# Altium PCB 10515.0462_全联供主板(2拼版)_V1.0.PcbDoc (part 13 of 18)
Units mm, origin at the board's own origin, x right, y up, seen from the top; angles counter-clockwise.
Board outline 282 x 198 mm, 2 copper layers (Top Layer, Bottom Layer); 716 components, 0 nets, 2364 pads, 1800 vias.
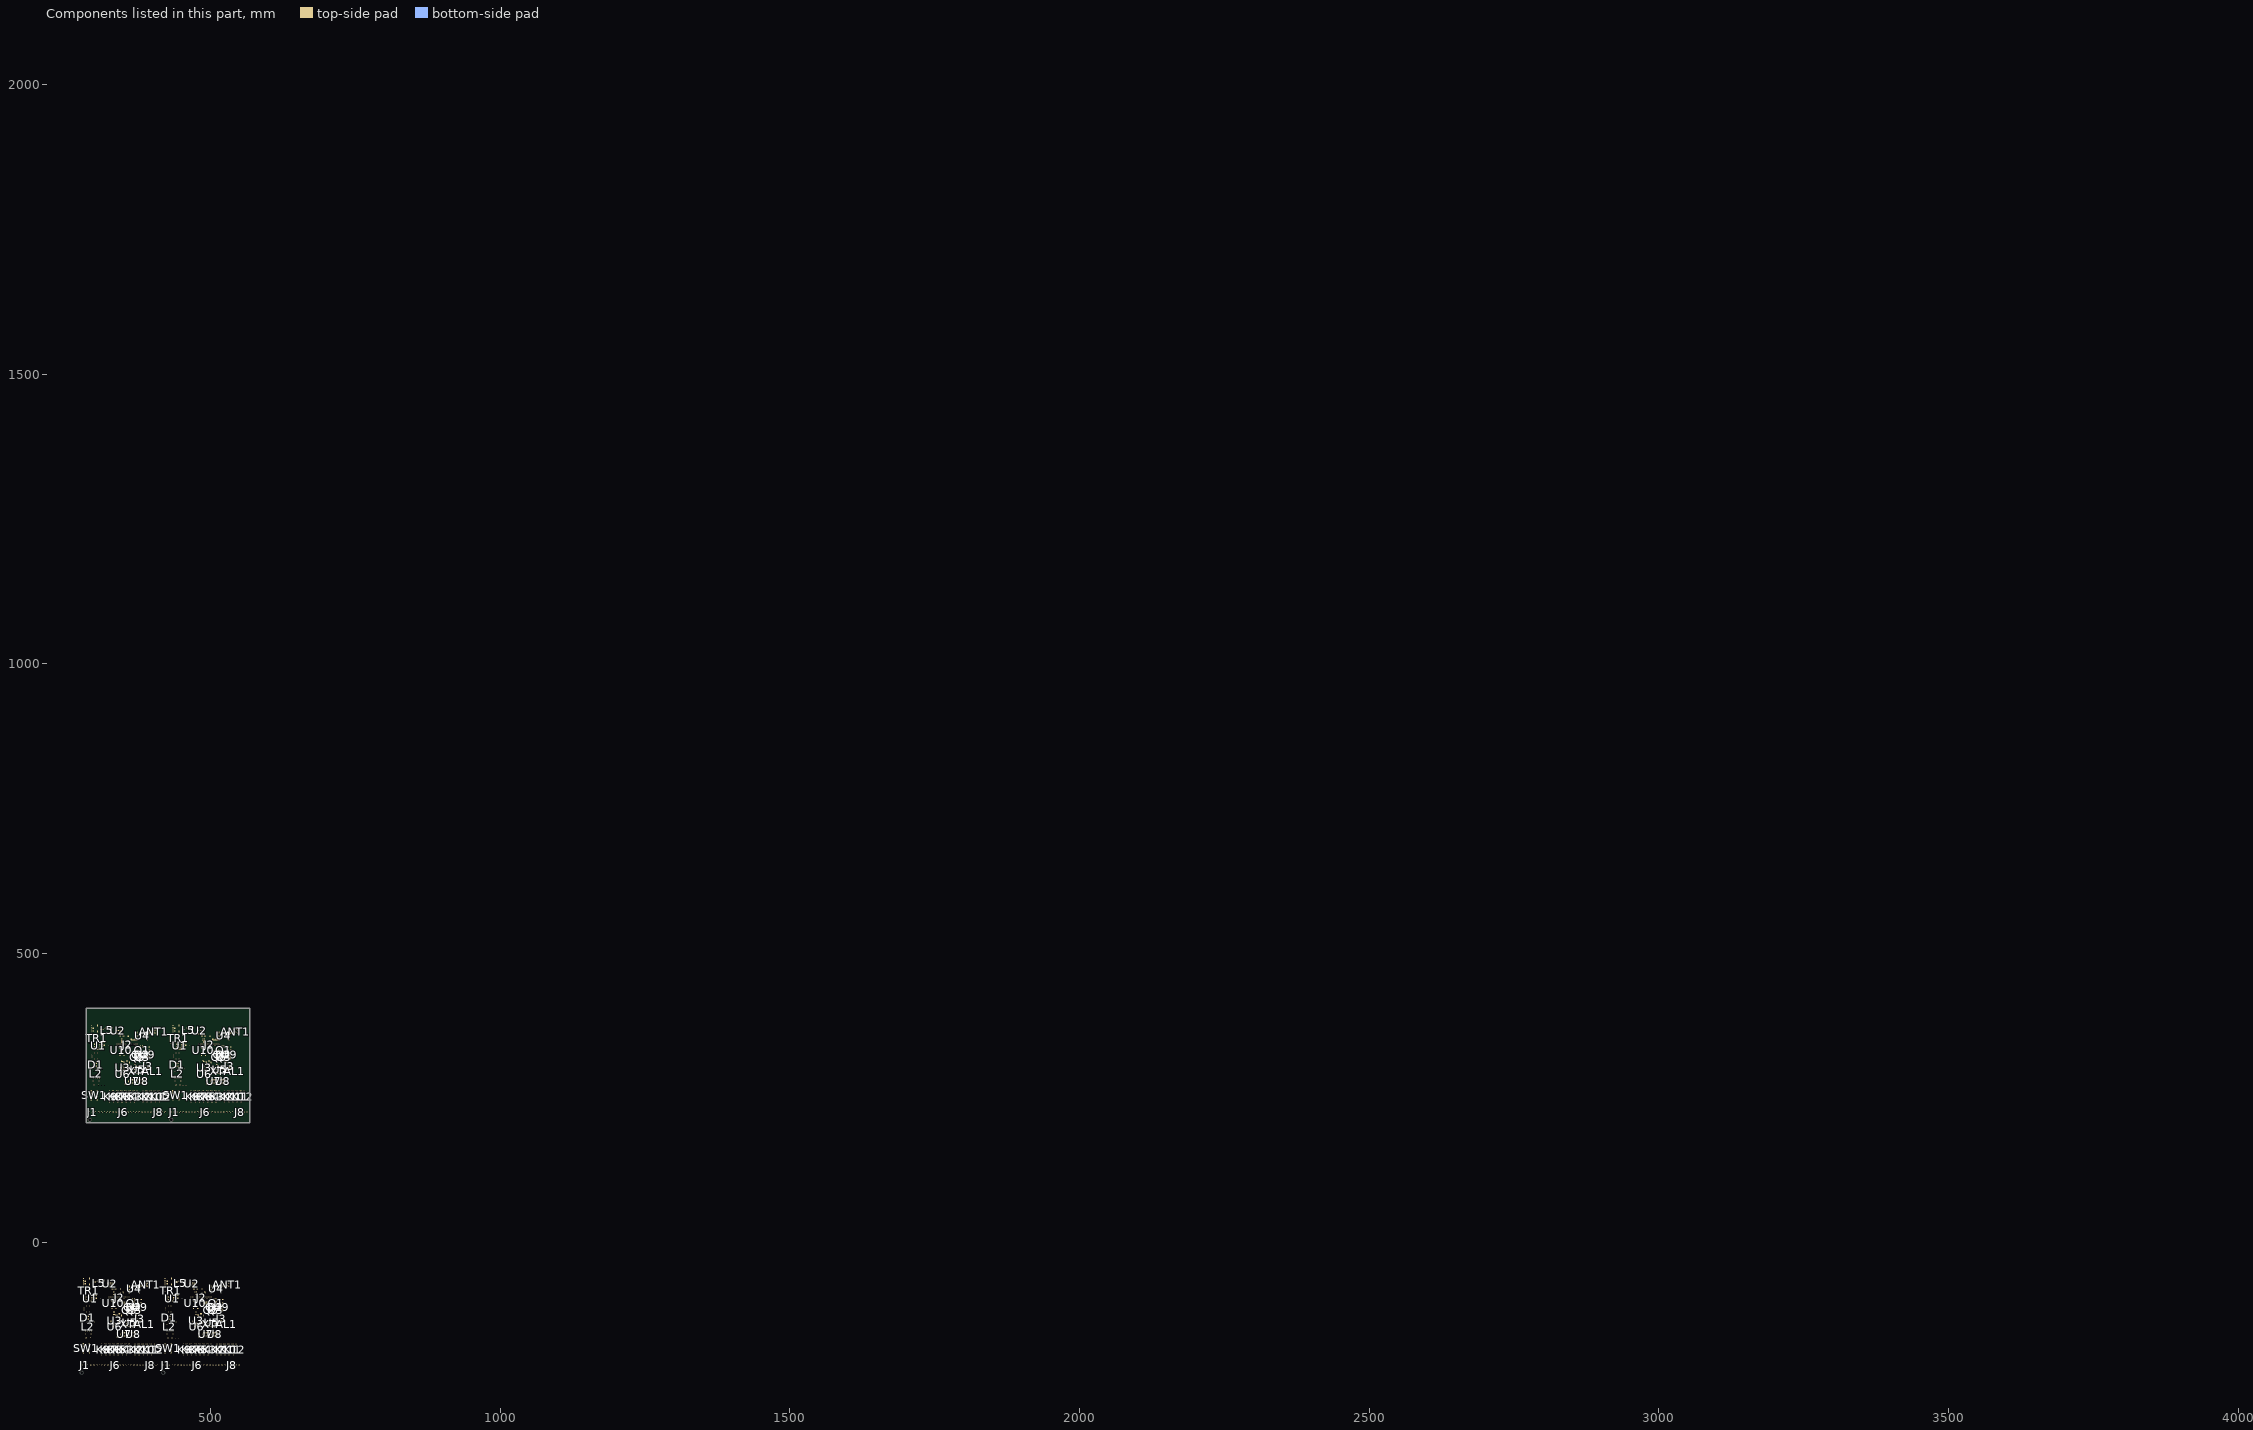
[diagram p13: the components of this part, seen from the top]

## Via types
v1: diameter 0.7, hole 0.4, Top Layer to Bottom Layer, tented both sides, 1800 vias

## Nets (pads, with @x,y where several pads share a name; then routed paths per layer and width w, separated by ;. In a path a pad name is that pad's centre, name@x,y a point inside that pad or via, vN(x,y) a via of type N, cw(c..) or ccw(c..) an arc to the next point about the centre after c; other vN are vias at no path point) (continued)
copper on no net: (continued)
  Top Layer w1.5: 274.137,-177.275 274.137,-179.477 ; 274.3,-175.667 278.491,-175.667 278.999,-176.175 278.11,-177.064 274.808,-177.064 ; 276.55,-177.064 275.298,-178.316 ; 277.951,-137.313 cw(c277.951,-134.711) 276.111,-136.551 ; 278.257,-135.662 ccw(c278.257,-138.697) 276.111,-136.551 ; 278.364,-174.397 274.681,-174.397 273.665,-175.413 273.665,-197.511 281.476,-205.321 ; 278.745,-178.334 278.727,-178.316 275.298,-178.316 ; 278.999,-188.113 280.142,-189.256 280.142,-192.304 ; 280.024,-67.088 280.024,-64.528 ; 280.024,-61.099 282.69,-61.099 283.554,-61.963 283.554,-65.748 ; 280.049,-70.542 283.548,-70.542 ; 280.142,-194.209 280.65,-194.209 288.016,-201.575 ; 280.557,-93.529 283.28,-93.529 ; 280.65,-135.535 284.587,-131.598 285.984,-131.598 285.984,-131.852 282.174,-135.662 277,-135.662 276.111,-136.551 ; 280.86,-139.301 ccw(c283.699,-136.462) 283.699,-140.477 ; 281.192,-115.353 283.317,-115.353 ; 281.192,-112.353 284.401,-112.353 285.677,-111.077 285.677,-108.622 285.677,-109.486 282.809,-112.353 ; 281.301,-138.329 279.888,-138.329 ; 282.809,-211.227 282.809,-205.418 274.137,-196.746 274.137,-179.477 ; v1(283.318,-126.457) 286.088,-126.457 ; 283.326,-93.484 283.326,-90.106 283.605,-89.826 ; 283.326,-90.622 cw(c284.4,-90.622) 283.64,-89.862 ; 283.554,-75.776 283.554,-70.548 ; 283.571,-147.855 283.571,-151.664 283.571,-156.871 ; 283.942,-66.066 cw(c286.674,-68.798) 286.674,-64.934 ; 284.097,-162.546 ccw(c284.951,-161.692) 284.951,-162.899 ; 284.887,-116.924 cw(c283.101,-118.709) 285.627,-118.709 ; 285.123,-110.04 ccw(c283.905,-108.822) 285.627,-108.822 ; 285.54,-202.781 285.54,-202.913 286.391,-203.764 286.391,-210.295 287.081,-210.984 ; 285.677,-118.009 285.677,-117.713 283.317,-115.353 ; 285.727,-119.109 ccw(c289.195,-119.109) 286.743,-121.562 ; 287,-151.664 290.683,-151.664 ; 287.766,259.32 287.766,257.118 ; 287.929,260.928 292.12,260.928 292.628,260.42 291.739,259.531 288.437,259.531 ; 288.917,-126.487 288.917,-123.736 285.677,-120.496 285.677,-118.909 285.677,-116.432 284.599,-115.353 283.317,-115.353 ; 289.286,-132.741 290.175,-133.63 ; 289.298,-132.437 cw(c289.298,-134.248) 290.578,-132.968 ; 289.425,-131.687 291.368,-133.63 ; 289.499,-171.689 284.951,-167.14 ; 289.499,-170.546 288.461,-169.507 ; 289.774,-176.449 288.461,-175.136 288.461,-172.238 ; 289.858,-185.255 290.366,-185.763 300.272,-185.763 ; 289.921,-189.256 302.665,-189.256 ; 290.048,-133.63 291.114,-133.63 ; 290.134,-185.614 290.134,-186.04 290.769,-186.675 301.944,-186.675 304.802,-183.817 ; 290.179,259.531 288.927,258.279 ; 290.261,-185.614 291.064,-184.811 ; 290.302,-184.811 303.808,-184.811 ; 290.677,-109.373 291.953,-110.649 291.953,-117.633 290.677,-118.909 290.677,-108.622 ; 290.677,-102.486 290.677,-108.622 ; 290.727,-108.822 ccw(c292.177,-108.822) 291.152,-109.848 ; 290.81,-187.986 302.582,-187.986 307.066,-183.502 ; 290.86,-133.63 293.604,-133.63 ; 290.89,-62.383 288.339,-64.934 287.762,-64.934 ; 291.58,299.282 cw(c291.58,301.884) 289.74,300.044 ; 291.699,-147.977 cw(c291.699,-151.647) 294.294,-149.052 ; 291.699,-147.727 292.969,-147.727 294.112,-148.87 294.112,-151.664 294.112,-156.465 292.352,-158.225 292.352,-164.566 ; 291.728,-140.479 ccw(c292.133,-136.985) 294.62,-139.472 ; 291.785,-147.962 cw(c292.382,-149.584) 293.604,-148.362 ; 291.886,300.933 ccw(c291.886,297.898) 289.74,300.044 ; 291.993,262.198 288.31,262.198 287.294,261.182 287.294,239.084 295.104,231.274 ; 292.023,-103.601 297.611,-103.601 ; 292.175,-164.14 ccw(c288.479,-160.444) 293.706,-160.444 ; 292.207,-105.055 293.477,-105.055 291.699,-103.277 291.699,-107.214 ; 292.352,-164.066 ccw(c292.352,-162.859) 293.205,-163.713 ; 292.374,258.261 292.356,258.279 288.927,258.279 ; 292.461,-213.398 cw(c295.375,-213.398) 293.315,-211.338 ; 292.461,-103.601 ccw(c292.461,-99.86) 295.106,-102.505 ; 292.628,248.482 293.771,247.339 293.771,244.291 ; 292.961,-218.816 292.961,-217.45 ; 293.059,-102.505 ccw(c295.704,-99.86) 295.704,-103.601 ; 293.527,-156.692 ccw(c292.113,-155.278) 294.112,-155.278 ; 293.652,369.508 293.652,372.068 ; 293.652,375.497 296.319,375.497 297.183,374.633 297.183,370.848 ; 293.678,366.053 297.177,366.053 ; 293.706,-156.871 293.706,-163.212 292.352,-164.566 ; 293.771,242.386 294.279,242.386 301.645,235.02 ; 294.186,343.066 296.909,343.066 ; 294.279,301.06 298.216,304.997 299.613,304.997 299.613,304.743 295.803,300.933 290.629,300.933 289.74,300.044 ; 294.489,297.294 ccw(c297.328,300.133) 297.328,296.118 ; 294.821,321.242 296.946,321.242 ; 294.821,324.242 298.029,324.242 299.306,325.518 299.306,327.973 299.306,327.11 296.438,324.242 ; 294.93,298.266 293.517,298.266 ; 295.21,-102.497 ccw(c297.611,-100.438) 297.611,-103.601 ; 296.438,225.368 296.438,231.177 287.766,239.849 287.766,257.118 ; v1(296.947,310.139) 299.717,310.139 ; 296.954,343.112 296.954,346.49 297.234,346.769 ; 296.954,345.974 cw(c298.029,345.974) 297.269,346.734 ; 297.183,360.82 297.183,366.048 ; 297.2,288.74 297.2,284.931 297.2,279.724 ; 297.571,370.529 cw(c300.303,367.798) 300.303,371.661 ; 297.726,274.05 ccw(c298.579,274.903) 298.579,273.696 ; 297.795,-164.491 297.72,-164.566 ; 297.961,-210.984 297.961,-208.439 311.671,-194.729 311.671,-192.812 ; 298.516,319.672 cw(c296.73,317.886) 299.256,317.886 ; 298.684,-138.71 ccw(c297.023,-137.048) 299.319,-136.551 ; 298.752,326.556 ccw(c297.534,327.773) 299.256,327.773 ; 299.008,-102.204 297.611,-103.601 ; 299.168,233.814 299.168,233.683 300.02,232.831 300.02,226.301 300.71,225.611 ; 299.306,318.586 299.306,318.882 296.946,321.242 ; 299.356,317.486 ccw(c302.824,317.486) 300.372,315.034 ; 299.573,-186.675 299.573,-186.462 ; 300.629,284.931 304.312,284.931 ; 300.97,-219.314 301.426,-218.858 ; 301.138,-186.675 302.875,-184.938 ; 302.05,-185.763 300.272,-185.763 ; 302.157,-186.462 299.573,-186.462 ; 302.211,-81.208 ccw(c303.675,-79.744) v1@303.675,-81.814 ; v1@302.514,-81.199 303.129,-81.814 305.542,-81.814 312.781,-81.814 ; 302.546,310.108 302.546,312.86 299.306,316.1 299.306,317.686 299.306,320.164 298.227,321.242 296.946,321.242 ; 302.875,-169.825 302.875,-164.491 ; 302.915,303.854 303.804,302.965 ; 302.927,304.158 cw(c302.927,302.347) 304.207,303.628 ; 302.961,-218.656 302.961,-217.323 ; 302.961,-210.984 302.961,-217.323 ; 303.054,304.908 304.996,302.965 ; 303.128,264.906 298.579,269.455 ; 303.128,266.049 302.089,267.088 ; 303.402,260.146 302.089,261.459 302.089,264.357 ; 303.453,-82.138 ccw(c303.637,-81.953) 303.637,-82.214 ; 303.486,251.34 303.994,250.832 313.9,250.832 ; 303.55,247.339 316.294,247.339 ; 303.677,302.965 304.742,302.965 ; 303.763,250.981 303.763,250.555 304.398,249.92 315.573,249.92 318.431,252.778 ; 303.88,-174.905 303.88,-174.016 ; 303.89,250.981 304.693,251.784 ; 303.931,251.784 317.437,251.784 ; 303.944,-73.666 cw(c301.467,-76.143) 304.971,-76.143 ; 304.306,327.222 305.582,325.946 305.582,318.962 304.306,317.686 304.306,327.973 ; 304.306,334.109 304.306,327.973 ; 304.356,327.773 ccw(c305.806,327.773) 304.78,326.748 ; 304.439,248.609 316.211,248.609 320.695,253.093 ; 304.488,302.965 307.233,302.965 ; 304.519,374.212 301.967,371.661 301.391,371.661 ; 305.328,288.618 cw(c305.328,284.949) 307.923,287.544 ; 305.328,288.868 306.598,288.868 307.741,287.725 307.741,284.931 307.741,280.131 305.98,278.37 305.98,272.029 ; 305.357,296.117 ccw(c305.762,299.61) 308.249,297.123 ; 305.414,288.634 cw(c306.01,287.011) 307.233,288.234 ; 305.437,-183.944 306.031,-184.537 ; 305.652,332.994 311.24,332.994 ; 305.804,272.456 ccw(c302.108,276.152) 307.334,276.152 ; 305.836,331.54 307.106,331.54 305.328,333.318 305.328,329.381 ; 305.923,-179.477 305.288,-178.842 ; 305.98,272.529 ccw(c305.98,273.736) 306.834,272.883 ; 306.006,-182.779 305.923,-182.696 304.802,-183.817 ; 306.09,332.994 ccw(c306.09,336.735) 308.735,334.09 ; 306.09,223.197 cw(c309.004,223.197) 306.943,225.258 ; 306.094,-183.966 313.543,-183.966 ; 306.304,-79.274 304.971,-77.94 ; 306.59,217.779 306.59,219.145 ; 306.688,334.09 ccw(c309.333,336.735) 309.333,332.994 ; 307.155,279.904 ccw(c305.742,281.317) 307.741,281.317 ; 307.334,279.724 307.334,273.383 305.98,272.029 ; 307.657,-186.252 314.051,-186.252 ; 307.955,-183.966 302.665,-189.256 ; 307.961,-210.984 307.961,-206.694 318.856,-195.799 318.856,-192.939 ; 308.574,-182.255 306.453,-182.255 ; 308.839,334.098 ccw(c311.24,336.157) 311.24,332.994 ; 308.971,-183.966 308.971,-184.938 304.653,-189.256 303.764,-189.256 ; 309.098,-182.779 307.066,-180.747 ; 310.484,-185.065 375.508,-185.065 ; 311.424,272.104 311.348,272.029 ; 311.59,225.611 311.59,228.156 325.3,241.866 325.3,243.783 ; 311.671,-186.252 314.051,-186.252 ; 311.765,-185.827 311.765,-185.7 ; 311.765,-183.541 306.05,-189.256 303.764,-189.256 ; 311.777,-186.008 cw(c314.054,-188.285) 314.054,-185.065 ; 312.063,-183.966 307.066,-178.969 ; 312.288,-185.065 cw(c312.288,-185.788) 312.998,-185.656 ; 312.313,297.886 ccw(c310.651,299.547) 312.948,300.044 ; 312.637,334.391 311.24,332.994 ; 312.961,-218.585 312.961,-217.536 ; 312.961,-210.984 312.961,-217.323 ; 313.202,249.92 313.202,250.133 ; 313.83,-186.252 314.051,-186.252 ; 313.83,-183.966 312.204,-182.34 ; 314.599,217.282 315.054,217.737 ; 314.767,249.92 316.504,251.657 ; 315.575,-158.014 317.226,-159.665 333.99,-159.665 336.271,-161.946 337.92,-161.946 334.609,-158.635 317.734,-158.635 316.38,-157.281 316.38,-156.871 ; 315.678,250.832 313.9,250.832 ; 315.702,-186.252 315.702,-185.838 312.204,-182.34 ; 315.786,250.133 313.202,250.133 ; 315.84,355.388 ccw(c317.303,356.851) v1@317.303,354.781 ; v1@316.143,355.397 316.758,354.781 319.171,354.781 326.41,354.781 ; 316.362,-153.703 316.362,-82.982 315.194,-81.814 313.67,-81.814 ; 316.362,-84.354 313.822,-81.814 313.67,-81.814 ; 316.38,-157.803 316.38,-156.871 ; 316.38,-153.712 316.38,-155.855 ; 316.464,-158.776 315.448,-157.76 315.448,-84.862 312.781,-82.195 312.781,-81.814 ; 316.473,-185.065 cw(c316.473,-188.285) 318.75,-186.008 ; 316.504,266.77 316.504,272.104 ; 316.59,217.939 316.59,219.272 ; 316.59,225.611 316.59,219.272 ; 317.082,354.458 ccw(c317.266,354.642) 317.266,354.381 ; 317.509,261.69 317.509,262.579 ; 317.573,362.93 cw(c315.095,360.452) 318.599,360.452 ; 317.961,-210.984 317.961,-204.396 321.914,-200.443 322.433,-200.443 ; 317.961,-204.916 322.433,-200.443 ; 318.962,-186.008 cw(c321.239,-188.285) 321.239,-185.065 ; 319.066,252.651 319.659,252.058 ; 319.16,-158.635 316.38,-155.855 ; 319.552,257.118 318.917,257.753 ; 319.635,253.816 319.552,253.899 318.431,252.778 ; 319.723,252.629 327.172,252.629 ; 319.933,357.321 318.599,358.655 ; 320.655,-156.617 318.623,-154.585 318.623,-81.052 ; 321.286,250.343 327.68,250.343 ; 321.584,252.629 316.294,247.339 ; 321.59,225.611 321.59,229.901 332.485,240.796 332.485,243.656 ; 322.052,-200.332 326.016,-196.368 ; 322.202,254.341 320.082,254.341 ; 322.6,252.629 322.6,251.657 318.282,247.339 317.393,247.339 ; 322.727,253.816 320.695,255.848 ; 322.961,-218.618 322.961,-217.323 ; 322.961,-210.984 322.961,-217.323 ; 323.633,-185.065 cw(c323.633,-188.285) 325.91,-186.008 ; 324.113,251.53 389.137,251.53 ; 325.1,-219.462 324.496,-218.858 ; 325.3,250.343 327.68,250.343 ; 325.394,250.768 325.394,250.895 ; 325.394,253.054 319.679,247.339 317.393,247.339 ; 325.406,250.587 cw(c327.683,248.311) 327.683,251.53 ; 325.692,252.629 320.695,257.626 ; 325.917,251.53 cw(c325.917,250.808) 326.627,250.94 ; 326.016,-192.939 326.016,-196.368 ; 326.122,-186.008 cw(c328.399,-188.285) 328.399,-185.065 ; 326.59,218.01 326.59,219.06 ; 326.59,225.611 326.59,219.272 ; 327.459,250.343 327.68,250.343 ; 327.459,252.629 325.833,254.255 ; 327.961,-210.984 327.961,-204.982 333.175,-199.768 333.175,-193.066 ; 329.204,278.581 330.855,276.93 347.619,276.93 349.9,274.649 351.549,274.649 348.238,277.96 331.363,277.96 330.009,279.315 330.009,279.724 ; 329.331,250.343 329.331,250.757 325.833,254.255 ; 329.991,282.892 329.991,353.614 328.823,354.781 327.299,354.781 ; 329.991,352.241 327.451,354.781 327.299,354.781 ; 330.009,278.793 330.009,279.724 ; 330.009,282.884 330.009,280.74 ; 330.093,277.819 329.077,278.835 329.077,351.733 326.41,354.4 326.41,354.781 ; 330.102,251.53 cw(c330.102,248.311) 332.379,250.587 ; 330.793,-185.065 cw(c330.793,-188.285) 333.069,-186.008 ; 331.59,225.611 331.59,232.199 335.542,236.152 336.062,236.152 ; 331.59,231.68 336.062,236.152 ; 332.591,250.587 cw(c334.868,248.311) 334.868,251.53 ; 332.789,277.96 330.009,280.74 ; 332.961,-218.778 332.961,-217.323 ; 332.961,-210.984 332.961,-217.323 ; 333.282,-186.008 cw(c335.558,-188.285) 335.558,-185.065 ; 334.284,279.978 332.252,282.01 332.252,355.543 ; 335.681,236.264 339.645,240.227 ; 336.59,217.977 336.59,219.272 ; 336.59,225.611 336.59,219.272 ; 337.262,251.53 cw(c337.262,248.311) 339.539,250.587 ; 337.952,-185.065 cw(c337.952,-188.285) 340.229,-186.008 ; 337.961,-210.984 337.961,-203.745 340.335,-201.371 340.335,-193.066 ; 338.729,217.133 338.125,217.737 ; 339.645,243.656 339.645,240.227 ; 339.751,250.587 cw(c342.027,248.311) 342.027,251.53 ; 340.441,-186.008 cw(c342.718,-188.285) 342.718,-185.065 ; 341.59,225.611 341.59,231.613 346.804,236.828 346.804,243.529 ; 342.961,-218.778 342.961,-217.254 ; 342.961,-210.984 342.961,-217.196 ; 344.421,251.53 cw(c344.421,248.311) 346.698,250.587 ; 345.112,-185.065 cw(c345.112,-188.285) 347.389,-186.008 ; 346.59,217.817 346.59,219.272 ; 346.59,225.611 346.59,219.272 ; 346.91,250.587 cw(c349.187,248.311) 349.187,251.53 ; 347.495,-210.518 347.495,-193.193 ; 347.495,-208.652 ccw(c350.294,-208.652) 348.315,-210.631 ; 347.601,-186.008 cw(c349.878,-188.285) 349.878,-185.065 ; 350.754,-219.53 351.426,-218.858 ; 351.581,251.53 cw(c351.581,248.311) 353.858,250.587 ; 351.59,225.611 351.59,232.85 353.964,235.224 353.964,243.529 ; 352.214,-185.065 cw(c352.214,-188.285) 354.491,-186.008 ; 352.961,-218.844 352.961,-217.323 ; 352.961,-210.984 352.961,-217.323 ; 354.07,250.587 cw(c356.347,248.311) 356.347,251.53 ; 354.597,-193.252 354.597,-203.744 357.961,-207.108 357.961,-210.984 ; 354.703,-186.008 cw(c356.98,-188.285) 356.98,-185.065 ; 355.072,-219.434 354.496,-218.858 ; 356.59,217.817 356.59,219.342 ; 356.59,225.611 356.59,219.399 ; 358.741,251.53 cw(c358.741,248.311) 361.017,250.587 ; 361.124,226.077 361.124,243.402 ; 361.124,227.944 ccw(c363.923,227.944) 361.943,225.965 ; 361.23,250.587 cw(c363.506,248.311) 363.506,251.53 ; 362.961,-218.712 362.961,-217.465 ; 362.961,-210.984 362.961,-217.196 ; 364.383,217.066 365.054,217.737 ; 365.843,251.53 cw(c365.843,248.311) 368.12,250.587 ; 366.59,217.751 366.59,219.272 ; 366.59,225.611 366.59,219.272 ; 367.38,-185.065 cw(c367.38,-187.851) 369.35,-185.881 ; 367.961,-210.984 367.961,-194.02 369.296,-192.685 ; 367.961,-195.733 369.456,-194.238 369.456,-192.812 ; 367.961,-194.62 369.456,-193.125 ; 368.226,243.343 368.226,232.851 371.59,229.487 371.59,225.611 ; 368.332,250.587 cw(c370.609,248.311) 370.609,251.53 ; 368.602,-193.979 cw(c369.456,-194.832) 369.456,-193.625 ; 368.701,217.161 368.125,217.737 ; 369.562,-185.881 cw(c371.532,-187.851) 371.532,-185.065 ; 372.961,-210.984 372.961,-217.132 ; 374.492,-185.065 cw(c374.492,-187.851) 376.462,-185.881 ; 375.714,-185.271 ccw(c376.568,-184.418) 376.568,-185.625 ; 376.421,-185.806 ccw(c375.508,-185.998) 375.508,-185.065 ; 376.568,-192.812 376.568,-201.966 377.961,-203.359 377.961,-210.984 ; 376.59,217.883 376.59,219.131 ; 376.59,225.611 376.59,219.399 ; 381.009,251.53 cw(c381.009,248.744) 382.979,250.714 ; 381.59,225.611 381.59,242.575 382.925,243.91 ; 381.59,240.862 383.085,242.358 383.085,243.783 ; 381.59,241.975 383.085,243.47 ; 382.231,242.617 cw(c383.085,241.763) 383.085,242.97 ; 383.019,-210.758 ccw(c381.408,-209.146) 383.687,-209.146 ; 383.191,250.714 cw(c385.161,248.744) 385.161,251.53 ; 383.687,-210.797 383.687,-192.939 ; 383.687,-186.125 385.746,-186.125 387.364,-187.743 387.364,-203.491 388.373,-204.5 388.373,-211.111 ; 386.59,225.611 386.59,219.463 ; 388.121,251.53 cw(c388.121,248.744) 390.091,250.714 ; 389.343,251.324 ccw(c390.197,252.178) 390.197,250.97 ; 390.05,250.79 ccw(c389.137,250.597) 389.137,251.53 ; 390.197,243.783 390.197,234.629 391.59,233.236 391.59,225.611 ; 390.799,-192.939 390.799,-202.227 393.373,-204.801 393.373,-211.111 ; 390.799,-186.625 cw(c390.799,-187.832) 391.653,-186.979 ; 390.799,-186.125 393.968,-189.294 393.968,-199.935 398.373,-204.34 398.373,-211.111 ; 396.648,225.838 ccw(c395.037,227.449) 397.316,227.449 ; 397.316,225.798 397.316,243.656 ; 397.316,250.47 399.374,250.47 400.993,248.852 400.993,233.104 402.002,232.095 402.002,225.484 ; 398.038,-192.812 398.038,-199.433 403.373,-204.768 403.373,-211.111 ; 398.038,-186.625 cw(c398.038,-190.962) 401.105,-187.895 ; 398.038,-186.125 399.335,-186.125 402.604,-189.394 ; 398.104,-186.61 cw(c398.895,-188.211) 400.158,-186.948 ; 402.604,-189.256 402.604,-197.522 408.373,-203.291 408.373,-211.111 ; 404.428,243.656 404.428,234.368 407.002,231.794 407.002,225.484 ; 404.428,249.97 cw(c404.428,248.763) 405.281,249.617 ; 404.428,250.47 407.597,247.301 407.597,236.66 412.002,232.255 412.002,225.484 ; 411.667,243.783 411.667,237.162 417.002,231.827 417.002,225.484 ; 411.667,249.97 cw(c411.667,245.633) 414.734,248.7 ; 411.667,250.47 412.963,250.47 416.233,247.201 ; 411.733,249.986 cw(c412.524,248.384) 413.787,249.647 ; 415.137,-177.275 415.137,-179.477 ; 415.3,-175.667 419.491,-175.667 419.999,-176.175 419.11,-177.064 415.808,-177.064 ; 416.233,247.339 416.233,239.073 422.002,233.304 422.002,225.484 ; 417.55,-177.064 416.298,-178.316 ; 418.951,-137.313 cw(c418.951,-134.711) 417.111,-136.551 ; 419.257,-135.662 ccw(c419.257,-138.697) 417.111,-136.551 ; 419.364,-174.397 415.681,-174.397 414.665,-175.413 414.665,-197.511 422.476,-205.321 ; 419.745,-178.334 419.727,-178.316 416.298,-178.316 ; 419.999,-188.113 421.142,-189.256 421.142,-192.304 ; 421.024,-67.088 421.024,-64.528 ; 421.024,-61.099 423.69,-61.099 424.554,-61.963 424.554,-65.748 ; 421.049,-70.542 424.548,-70.542 ; 421.142,-194.209 421.65,-194.209 429.016,-201.575 ; 421.557,-93.529 424.28,-93.529 ; 421.65,-135.535 425.587,-131.598 426.984,-131.598 426.984,-131.852 423.174,-135.662 418,-135.662 417.111,-136.551 ; 421.86,-139.301 ccw(c424.699,-136.462) 424.699,-140.477 ; 422.192,-115.353 424.317,-115.353 ; 422.192,-112.353 425.401,-112.353 426.677,-111.077 426.677,-108.622 426.677,-109.486 423.809,-112.353 ; 422.301,-138.329 420.888,-138.329 ; 423.809,-211.227 423.809,-205.418 415.137,-196.746 415.137,-179.477 ; v1(424.318,-126.457) 427.088,-126.457 ; 424.326,-93.484 424.326,-90.106 424.605,-89.826 ; 424.326,-90.622 cw(c425.4,-90.622) 424.64,-89.862 ; 424.554,-75.776 424.554,-70.548 ; 424.571,-147.855 424.571,-151.664 424.571,-156.871 ; 424.942,-66.066 cw(c427.674,-68.798) 427.674,-64.934 ; 425.097,-162.546 ccw(c425.951,-161.692) 425.951,-162.899 ; 425.887,-116.924 cw(c424.101,-118.709) 426.627,-118.709 ; 426.123,-110.04 ccw(c424.905,-108.822) 426.627,-108.822 ; 426.54,-202.781 426.54,-202.913 427.391,-203.764 427.391,-210.295 428.081,-210.984 ; 426.677,-118.009 426.677,-117.713 424.317,-115.353 ; 426.727,-119.109 ccw(c430.195,-119.109) 427.743,-121.562 ; 428,-151.664 431.683,-151.664 ; 428.766,259.32 428.766,257.118 ; 428.929,260.928 433.12,260.928 433.628,260.42 432.739,259.531 429.437,259.531 ; 429.917,-126.487 429.917,-123.736 426.677,-120.496 426.677,-118.909 426.677,-116.432 425.599,-115.353 424.317,-115.353 ; 430.286,-132.741 431.175,-133.63 ; 430.298,-132.437 cw(c430.298,-134.248) 431.578,-132.968 ; 430.425,-131.687 432.368,-133.63 ; 430.499,-171.689 425.951,-167.14 ; 430.499,-170.546 429.461,-169.507 ; 430.774,-176.449 429.461,-175.136 429.461,-172.238 ; 430.858,-185.255 431.366,-185.763 441.272,-185.763 ; 430.921,-189.256 443.665,-189.256 ; 431.048,-133.63 432.114,-133.63 ; 431.134,-185.614 431.134,-186.04 431.769,-186.675 442.944,-186.675 445.802,-183.817 ; 431.179,259.531 429.927,258.279 ; 431.261,-185.614 432.064,-184.811 ; 431.302,-184.811 444.808,-184.811 ; 431.677,-109.373 432.953,-110.649 432.953,-117.633 431.677,-118.909 431.677,-108.622 ; 431.677,-102.486 431.677,-108.622 ; 431.727,-108.822 ccw(c433.177,-108.822) 432.152,-109.848 ; 431.81,-187.986 443.582,-187.986 448.066,-183.502 ; 431.86,-133.63 434.604,-133.63 ; 431.89,-62.383 429.339,-64.934 428.762,-64.934 ; 432.58,299.282 cw(c432.58,301.884) 430.74,300.044 ; 432.699,-147.977 cw(c432.699,-151.647) 435.294,-149.052 ; 432.699,-147.727 433.969,-147.727 435.112,-148.87 435.112,-151.664 435.112,-156.465 433.352,-158.225 433.352,-164.566 ; 432.728,-140.479 ccw(c433.133,-136.985) 435.62,-139.472 ; 432.785,-147.962 cw(c433.382,-149.584) 434.604,-148.362 ; 432.886,300.933 ccw(c432.886,297.898) 430.74,300.044 ; 432.993,262.198 429.31,262.198 428.294,261.182 428.294,239.084 436.104,231.274 ; 433.023,-103.601 438.611,-103.601 ; 433.175,-164.14 ccw(c429.479,-160.444) 434.706,-160.444 ; 433.207,-105.055 434.477,-105.055 432.699,-103.277 432.699,-107.214 ; 433.352,-164.066 ccw(c433.352,-162.859) 434.205,-163.713 ; 433.374,258.261 433.356,258.279 429.927,258.279 ; 433.461,-213.398 cw(c436.375,-213.398) 434.315,-211.338 ; 433.461,-103.601 ccw(c433.461,-99.86) 436.106,-102.505 ; 433.628,248.482 434.771,247.339 434.771,244.291 ; 433.961,-218.816 433.961,-217.45 ; 434.059,-102.505 ccw(c436.704,-99.86) 436.704,-103.601 ; 434.527,-156.692 ccw(c433.113,-155.278) 435.112,-155.278 ; 434.652,369.508 434.652,372.068 ; 434.652,375.497 437.319,375.497 438.183,374.633 438.183,370.848 ; 434.678,366.053 438.177,366.053 ; 434.706,-156.871 434.706,-163.212 433.352,-164.566 ; 434.771,242.386 435.279,242.386 442.645,235.02 ; 435.186,343.066 437.909,343.066 ; 435.279,301.06 439.216,304.997 440.613,304.997 440.613,304.743 436.803,300.933 431.629,300.933 430.74,300.044 ; 435.489,297.294 ccw(c438.328,300.133) 438.328,296.118 ; 435.821,321.242 437.946,321.242 ; 435.821,324.242 439.029,324.242 440.306,325.518 440.306,327.973 440.306,327.11 437.438,324.242 ; 435.93,298.266 434.517,298.266 ; 436.21,-102.497 ccw(c438.611,-100.438) 438.611,-103.601 ; 437.438,225.368 437.438,231.177 428.766,239.849 428.766,257.118 ; v1(437.947,310.139) 440.717,310.139 ; 437.954,343.112 437.954,346.49 438.234,346.769 ; 437.954,345.974 cw(c439.029,345.974) 438.269,346.734 ; 438.183,360.82 438.183,366.048 ; 438.2,288.74 438.2,284.931 438.2,279.724 ; 438.571,370.529 cw(c441.303,367.798) 441.303,371.661 ; 438.726,274.05 ccw(c439.579,274.903) 439.579,273.696 ; 438.795,-164.491 438.72,-164.566 ; 438.961,-210.984 438.961,-208.439 452.671,-194.729 452.671,-192.812 ; 439.516,319.672 cw(c437.73,317.886) 440.256,317.886 ; 439.684,-138.71 ccw(c438.023,-137.048) 440.319,-136.551 ; 439.752,326.556 ccw(c438.534,327.773) 440.256,327.773 ; 440.008,-102.204 438.611,-103.601 ; 440.168,233.814 440.168,233.683 441.02,232.831 441.02,226.301 441.71,225.611 ; 440.306,318.586 440.306,318.882 437.946,321.242 ; 440.356,317.486 ccw(c443.824,317.486) 441.372,315.034 ; 440.573,-186.675 440.573,-186.462 ; 441.629,284.931 445.312,284.931 ; 441.97,-219.314 442.426,-218.858 ; 442.138,-186.675 443.875,-184.938 ; 443.05,-185.763 441.272,-185.763 ; 443.157,-186.462 440.573,-186.462 ; 443.211,-81.208 ccw(c444.675,-79.744) v1@444.675,-81.814 ; v1@443.514,-81.199 444.129,-81.814 446.542,-81.814 453.781,-81.814 ; 443.546,310.108 443.546,312.86 440.306,316.1 440.306,317.686 440.306,320.164 439.227,321.242 437.946,321.242 ; 443.875,-169.825 443.875,-164.491 ; 443.915,303.854 444.804,302.965 ; 443.927,304.158 cw(c443.927,302.347) 445.207,303.628 ; 443.961,-218.656 443.961,-217.323 ; 443.961,-210.984 443.961,-217.323 ; 444.054,304.908 445.996,302.965 ; 444.128,264.906 439.579,269.455 ; 444.128,266.049 443.089,267.088 ; 444.402,260.146 443.089,261.459 443.089,264.357 ; 444.453,-82.138 ccw(c444.637,-81.953) 444.637,-82.214 ; 444.486,251.34 444.994,250.832 454.9,250.832 ; 444.55,247.339 457.294,247.339 ; 444.677,302.965 445.742,302.965 ; 444.763,250.981 444.763,250.555 445.398,249.92 456.573,249.92 459.431,252.778 ; 444.88,-174.905 444.88,-174.016 ; 444.89,250.981 445.693,251.784 ; 444.931,251.784 458.437,251.784 ; 444.944,-73.666 cw(c442.467,-76.143) 445.971,-76.143 ; 445.306,327.222 446.582,325.946 446.582,318.962 445.306,317.686 445.306,327.973 ; 445.306,334.109 445.306,327.973 ; 445.356,327.773 ccw(c446.806,327.773) 445.78,326.748 ; 445.439,248.609 457.211,248.609 461.695,253.093 ; 445.488,302.965 448.233,302.965 ; 445.519,374.212 442.967,371.661 442.391,371.661 ; 446.328,288.618 cw(c446.328,284.949) 448.923,287.544 ; 446.328,288.868 447.598,288.868 448.741,287.725 448.741,284.931 448.741,280.131 446.98,278.37 446.98,272.029 ; 446.357,296.117 ccw(c446.762,299.61) 449.249,297.123 ; 446.414,288.634 cw(c447.01,287.011) 448.233,288.234 ; 446.437,-183.944 447.031,-184.537 ; 446.652,332.994 452.24,332.994 ; 446.804,272.456 ccw(c443.108,276.152) 448.334,276.152 ; 446.836,331.54 448.106,331.54 446.328,333.318 446.328,329.381 ; 446.923,-179.477 446.288,-178.842 ; 446.98,272.529 ccw(c446.98,273.736) 447.834,272.883 ; 447.006,-182.779 446.923,-182.696 445.802,-183.817 ; 447.09,223.197 cw(c450.004,223.197) 447.943,225.258 ; 447.09,332.994 ccw(c447.09,336.735) 449.735,334.09 ; 447.094,-183.966 454.543,-183.966 ; 447.304,-79.274 445.971,-77.94 ; 447.59,217.779 447.59,219.145 ; 447.688,334.09 ccw(c450.333,336.735) 450.333,332.994 ; 448.155,279.904 ccw(c446.742,281.317) 448.741,281.317 ; 448.334,279.724 448.334,273.383 446.98,272.029 ; 448.657,-186.252 455.051,-186.252 ; 448.955,-183.966 443.665,-189.256 ; 448.961,-210.984 448.961,-206.694 459.856,-195.799 459.856,-192.939 ; 449.574,-182.255 447.453,-182.255 ; 449.839,334.098 ccw(c452.24,336.157) 452.24,332.994 ; 449.971,-183.966 449.971,-184.938 445.653,-189.256 444.764,-189.256 ; 450.098,-182.779 448.066,-180.747 ; 451.484,-185.065 516.508,-185.065 ; 452.424,272.104 452.348,272.029 ; 452.59,225.611 452.59,228.156 466.3,241.866 466.3,243.783 ; 452.671,-186.252 455.051,-186.252 ; 452.765,-185.827 452.765,-185.7 ; 452.765,-183.541 447.05,-189.256 444.764,-189.256 ; 452.777,-186.008 cw(c455.054,-188.285) 455.054,-185.065 ; 453.063,-183.966 448.066,-178.969 ; 453.288,-185.065 cw(c453.288,-185.788) 453.998,-185.656 ; 453.313,297.886 ccw(c451.651,299.547) 453.948,300.044 ; 453.637,334.391 452.24,332.994 ; 453.961,-218.585 453.961,-217.536 ; 453.961,-210.984 453.961,-217.323 ; 454.202,249.92 454.202,250.133 ; 454.83,-186.252 455.051,-186.252 ; 454.83,-183.966 453.204,-182.34 ; 455.599,217.282 456.054,217.737 ; 455.767,249.92 457.504,251.657 ; 456.575,-158.014 458.226,-159.665 474.99,-159.665 477.271,-161.946 478.92,-161.946 475.609,-158.635 458.734,-158.635 457.38,-157.281 457.38,-156.871 ; 456.678,250.832 454.9,250.832 ; 456.702,-186.252 456.702,-185.838 453.204,-182.34 ; 456.786,250.133 454.202,250.133 ; 456.84,355.388 ccw(c458.303,356.851) v1@458.303,354.781 ; v1@457.143,355.397 457.758,354.781 460.171,354.781 467.41,354.781 ; 457.362,-153.703 457.362,-82.982 456.194,-81.814 454.67,-81.814 ; 457.362,-84.354 454.822,-81.814 454.67,-81.814 ; 457.38,-157.803 457.38,-156.871 ; 457.38,-153.712 457.38,-155.855 ; 457.464,-158.776 456.448,-157.76 456.448,-84.862 453.781,-82.195 453.781,-81.814 ; 457.473,-185.065 cw(c457.473,-188.285) 459.75,-186.008 ; 457.504,266.77 457.504,272.104 ; 457.59,217.939 457.59,219.272 ; 457.59,225.611 457.59,219.272 ; 458.082,354.458 ccw(c458.266,354.642) 458.266,354.381 ; 458.509,261.69 458.509,262.579 ; 458.573,362.93 cw(c456.095,360.452) 459.599,360.452 ; 458.961,-210.984 458.961,-204.396 462.914,-200.443 463.433,-200.443 ; 458.961,-204.916 463.433,-200.443 ; 459.962,-186.008 cw(c462.239,-188.285) 462.239,-185.065 ; 460.066,252.651 460.659,252.058 ; 460.16,-158.635 457.38,-155.855 ; 460.552,257.118 459.917,257.753 ; 460.635,253.816 460.552,253.899 459.431,252.778 ; 460.723,252.629 468.172,252.629 ; 460.933,357.321 459.599,358.655 ; 461.655,-156.617 459.623,-154.585 459.623,-81.052 ; 462.286,250.343 468.68,250.343 ; 462.584,252.629 457.294,247.339 ; 462.59,225.611 462.59,229.901 473.485,240.796 473.485,243.656 ; 463.052,-200.332 467.016,-196.368 ; 463.202,254.341 461.082,254.341 ; 463.6,252.629 463.6,251.657 459.282,247.339 458.393,247.339 ; 463.727,253.816 461.695,255.848 ; 463.961,-218.618 463.961,-217.323 ; 463.961,-210.984 463.961,-217.323 ; 464.633,-185.065 cw(c464.633,-188.285) 466.91,-186.008 ; 465.113,251.53 530.137,251.53 ; 466.1,-219.462 465.496,-218.858 ; 466.3,250.343 468.68,250.343 ; 466.394,250.768 466.394,250.895 ; 466.394,253.054 460.679,247.339 458.393,247.339 ; 466.406,250.587 cw(c468.683,248.311) 468.683,251.53 ; 466.692,252.629 461.695,257.626 ; 466.917,251.53 cw(c466.917,250.808) 467.627,250.94 ; 467.016,-192.939 467.016,-196.368 ; 467.122,-186.008 cw(c469.399,-188.285) 469.399,-185.065 ; 467.59,218.01 467.59,219.06 ; 467.59,225.611 467.59,219.272 ; 468.459,250.343 468.68,250.343 ; 468.459,252.629 466.833,254.255 ; 468.961,-210.984 468.961,-204.982 474.175,-199.768 474.175,-193.066 ; 470.204,278.581 471.855,276.93 488.619,276.93 490.9,274.649 492.549,274.649 489.238,277.96 472.363,277.96 471.009,279.315 471.009,279.724 ; 470.331,250.343 470.331,250.757 466.833,254.255 ; 470.991,282.892 470.991,353.614 469.823,354.781 468.299,354.781 ; 470.991,352.241 468.451,354.781 468.299,354.781 ; 471.009,278.793 471.009,279.724 ; 471.009,282.884 471.009,280.74 ; 471.093,277.819 470.077,278.835 470.077,351.733 467.41,354.4 467.41,354.781 ; 471.102,251.53 cw(c471.102,248.311) 473.379,250.587 ; 471.793,-185.065 cw(c471.793,-188.285) 474.069,-186.008 ; 472.59,225.611 472.59,232.199 476.542,236.152 477.062,236.152 ; 472.59,231.68 477.062,236.152 ; 473.591,250.587 cw(c475.868,248.311) 475.868,251.53 ; 473.789,277.96 471.009,280.74 ; 473.961,-218.778 473.961,-217.323 ; 473.961,-210.984 473.961,-217.323 ; 474.282,-186.008 cw(c476.558,-188.285) 476.558,-185.065 ; 475.284,279.978 473.252,282.01 473.252,355.543 ; 476.681,236.264 480.645,240.227 ; 477.59,217.977 477.59,219.272 ; 477.59,225.611 477.59,219.272 ; 478.262,251.53 cw(c478.262,248.311) 480.539,250.587 ; 478.952,-185.065 cw(c478.952,-188.285) 481.229,-186.008 ; 478.961,-210.984 478.961,-203.745 481.335,-201.371 481.335,-193.066 ; 479.729,217.133 479.125,217.737 ; 480.645,243.656 480.645,240.227 ; 480.751,250.587 cw(c483.027,248.311) 483.027,251.53 ; 481.441,-186.008 cw(c483.718,-188.285) 483.718,-185.065 ; 482.59,225.611 482.59,231.613 487.804,236.828 487.804,243.529 ; 483.961,-218.778 483.961,-217.254 ; 483.961,-210.984 483.961,-217.196 ; 485.421,251.53 cw(c485.421,248.311) 487.698,250.587 ; 486.112,-185.065 cw(c486.112,-188.285) 488.389,-186.008 ; 487.59,217.817 487.59,219.272 ; 487.59,225.611 487.59,219.272 ; 487.91,250.587 cw(c490.187,248.311) 490.187,251.53 ; 488.495,-210.518 488.495,-193.193 ; 488.495,-208.652 ccw(c491.294,-208.652) 489.315,-210.631 ; 488.601,-186.008 cw(c490.878,-188.285) 490.878,-185.065 ; 491.754,-219.53 492.426,-218.858 ; 492.581,251.53 cw(c492.581,248.311) 494.858,250.587 ; 492.59,225.611 492.59,232.85 494.964,235.224 494.964,243.529 ; 493.214,-185.065 cw(c493.214,-188.285) 495.491,-186.008 ; 493.961,-218.844 493.961,-217.323 ; 493.961,-210.984 493.961,-217.323 ; 495.07,250.587 cw(c497.347,248.311) 497.347,251.53 ; 495.597,-193.252 495.597,-203.744 498.961,-207.108 498.961,-210.984 ; 495.703,-186.008 cw(c497.98,-188.285) 497.98,-185.065 ; 496.072,-219.434 495.496,-218.858 ; 497.59,217.817 497.59,219.342 ; 497.59,225.611 497.59,219.399 ; 499.741,251.53 cw(c499.741,248.311) 502.017,250.587 ; 502.124,226.077 502.124,243.402 ; 502.124,227.944 ccw(c504.923,227.944) 502.943,225.965 ; 502.23,250.587 cw(c504.506,248.311) 504.506,251.53 ; 503.961,-218.712 503.961,-217.465 ; 503.961,-210.984 503.961,-217.196 ; 505.383,217.066 506.054,217.737 ; 506.843,251.53 cw(c506.843,248.311) 509.12,250.587 ; 507.59,217.751 507.59,219.272 ; 507.59,225.611 507.59,219.272 ; 508.38,-185.065 cw(c508.38,-187.851) 510.35,-185.881 ; 508.961,-210.984 508.961,-194.02 510.296,-192.685 ; 508.961,-195.733 510.456,-194.238 510.456,-192.812 ; 508.961,-194.62 510.456,-193.125 ; 509.226,243.343 509.226,232.851 512.59,229.487 512.59,225.611 ; 509.332,250.587 cw(c511.609,248.311) 511.609,251.53 ; 509.602,-193.979 cw(c510.456,-194.832) 510.456,-193.625 ; 509.701,217.161 509.125,217.737 ; 510.562,-185.881 cw(c512.532,-187.851) 512.532,-185.065 ; 513.961,-210.984 513.961,-217.132 ; 515.492,-185.065 cw(c515.492,-187.851) 517.462,-185.881 ; 516.714,-185.271 ccw(c517.568,-184.418) 517.568,-185.625 ; 517.421,-185.806 ccw(c516.508,-185.998) 516.508,-185.065 ; 517.568,-192.812 517.568,-201.966 518.961,-203.359 518.961,-210.984 ; 517.59,217.883 517.59,219.131 ; 517.59,225.611 517.59,219.399 ; 522.009,251.53 cw(c522.009,248.744) 523.979,250.714 ; 522.59,225.611 522.59,242.575 523.925,243.91 ; 522.59,240.862 524.085,242.358 524.085,243.783 ; 522.59,241.975 524.085,243.47 ; 523.231,242.617 cw(c524.085,241.763) 524.085,242.97 ; 524.019,-210.758 ccw(c522.408,-209.146) 524.687,-209.146 ; 524.191,250.714 cw(c526.161,248.744) 526.161,251.53 ; 524.687,-210.797 524.687,-192.939 ; 524.687,-186.125 526.746,-186.125 528.364,-187.743 528.364,-203.491 529.373,-204.5 529.373,-211.111 ; 527.59,225.611 527.59,219.463 ; 529.121,251.53 cw(c529.121,248.744) 531.091,250.714 ; 530.343,251.324 ccw(c531.197,252.178) 531.197,250.97 ; 531.05,250.79 ccw(c530.137,250.597) 530.137,251.53 ; 531.197,243.783 531.197,234.629 532.59,233.236 532.59,225.611 ; 531.799,-192.939 531.799,-202.227 534.373,-204.801 534.373,-211.111 ; 531.799,-186.625 cw(c531.799,-187.832) 532.653,-186.979 ; 531.799,-186.125 534.968,-189.294 534.968,-199.935 539.373,-204.34 539.373,-211.111 ; 537.648,225.838 ccw(c536.037,227.449) 538.316,227.449 ; 538.316,225.798 538.316,243.656 ; 538.316,250.47 540.374,250.47 541.993,248.852 541.993,233.104 543.002,232.095 543.002,225.484 ; 539.038,-192.812 539.038,-199.433 544.373,-204.768 544.373,-211.111 ; 539.038,-186.625 cw(c539.038,-190.962) 542.105,-187.895 ; 539.038,-186.125 540.335,-186.125 543.604,-189.394 ; 539.104,-186.61 cw(c539.895,-188.211) 541.158,-186.948 ; 543.604,-189.256 543.604,-197.522 549.373,-203.291 549.373,-211.111 ; 545.428,243.656 545.428,234.368 548.002,231.794 548.002,225.484 ; 545.428,249.97 cw(c545.428,248.763) 546.281,249.617 ; 545.428,250.47 548.597,247.301 548.597,236.66 553.002,232.255 553.002,225.484 ; 552.667,243.783 552.667,237.162 558.002,231.827 558.002,225.484 ; 552.667,249.97 cw(c552.667,245.633) 555.734,248.7 ; 552.667,250.47 553.963,250.47 557.233,247.201 ; 552.733,249.986 cw(c553.524,248.384) 554.787,249.647 ; 557.233,247.339 557.233,239.073 563.002,233.304 563.002,225.484 ; 274.137,-179.477 275.298,-178.316 ; 276.111,-136.551 276.873,-137.313 280.285,-137.313 283.699,-140.727 282.286,-140.727 279.888,-138.329 ; 276.111,-136.551 277.889,-138.329 279.888,-138.329 ; 279.571,-196.812 278.11,-195.352 278.11,-187.564 278.999,-186.675 278.999,-196.241 279.571,-196.812 ; 279.571,-196.812 287.081,-204.323 287.081,-210.984 ; 280.142,-192.304 288.016,-200.178 288.016,-201.575 ; 280.142,-192.304 280.142,-195.479 287.081,-202.418 287.081,-210.984 ; 281.476,-205.321 282.081,-205.927 282.081,-210.984 281.476,-210.379 281.476,-205.321 ; 283.554,-65.748 284.126,-66.32 288.016,-66.32 ; 283.554,-65.748 284.368,-64.934 287.762,-64.934 ; 283.571,-156.871 283.571,-162.02 284.951,-163.399 ; 283.571,-156.871 284.951,-158.25 284.951,-163.399 ; 284.951,-167.14 283.698,-165.888 283.698,-164.745 284.951,-163.492 284.951,-163.399 ; 284.951,-167.14 284.951,-165.997 ; 284.951,-165.997 288.461,-169.507 ; 284.951,-165.997 284.951,-163.399 ; 284.951,-163.399 284.951,-164.473 289.499,-169.022 ; 287.081,-210.984 288.016,-210.049 288.016,-201.575 ; 287.762,-64.934 289.402,-64.934 290.81,-63.526 ; 287.766,257.118 288.927,258.279 ; 288.016,-66.32 289.667,-66.32 290.81,-65.177 290.81,-63.526 ; 288.016,-66.32 290.81,-63.526 ; 288.461,-172.238 288.461,-173.444 289.499,-174.483 ; 288.461,-172.238 288.461,-169.507 ; 289.499,-176.175 290.937,-177.613 290.937,-178.08 291.064,-177.953 291.064,-173.635 ; 289.499,-176.175 291.064,-174.61 291.064,-173.635 ; 289.499,-176.175 289.499,-169.022 ; 289.499,-176.175 289.499,-174.483 ; 289.499,-174.483 290.429,-173.553 290.429,-169.952 ; 289.499,-169.022 290.429,-169.952 ; 289.74,300.044 290.502,299.282 293.914,299.282 297.328,295.868 295.915,295.868 293.517,298.266 ; 289.74,300.044 291.518,298.266 293.517,298.266 ; 290.429,-169.952 291.064,-170.587 291.064,-173.635 ; 290.677,-108.622 290.677,-108.236 291.699,-107.214 ; 291.699,-107.214 294.747,-104.166 297.046,-104.166 297.611,-103.601 ; 292.352,-164.566 293.292,-165.507 296.779,-165.507 297.72,-164.566 ; 292.352,-164.566 297.72,-164.566 ; 292.961,-217.45 295.12,-219.609 ; 292.961,-217.45 292.961,-216.561 ; 292.961,-216.561 292.961,-210.984 292.961,-210.6 292.461,-211.1 292.461,-218.339 293.731,-219.609 295.12,-219.609 ; 292.961,-216.561 295.258,-218.858 301.426,-218.858 ; 293.199,239.783 291.739,241.243 291.739,249.031 292.628,249.92 292.628,240.354 293.199,239.783 ; 293.199,239.783 300.71,232.273 300.71,225.611 ; 293.604,-133.63 296.398,-133.63 299.319,-136.551 ; 293.604,-133.63 294.747,-133.63 297.668,-136.551 299.319,-136.551 ; 293.771,244.291 301.645,236.417 301.645,235.02 ; 293.771,244.291 293.771,241.116 300.71,234.178 300.71,225.611 ; 295.104,231.274 295.71,230.669 295.71,225.611 295.104,226.216 295.104,231.274 ; 295.12,-219.609 305.247,-219.609 ; 297.183,370.848 297.755,370.275 301.645,370.275 ; 297.183,370.848 297.996,371.661 301.391,371.661 ; 297.2,279.724 297.2,274.575 298.579,273.196 ; 297.2,279.724 298.579,278.345 298.579,273.196 ; 298.579,269.455 297.327,270.707 297.327,271.85 298.579,273.103 298.579,273.196 ; 298.579,269.455 298.579,270.598 ; 298.579,270.598 302.089,267.088 ; 298.579,270.598 298.579,273.196 ; 298.579,273.196 298.579,272.122 303.128,267.573 ; 299.319,-136.551 299.319,-137.821 298.684,-138.456 293.97,-138.456 291.699,-140.727 293.365,-140.727 294.62,-139.472 297.922,-139.472 299.446,-137.948 299.446,-136.678 299.319,-136.551 ; 299.573,-186.462 300.272,-185.763 ; 300.71,225.611 301.645,226.546 301.645,235.02 ; 301.391,371.661 303.03,371.661 304.439,373.069 ; 301.426,-218.858 302.961,-217.323 ; 301.426,-218.858 304.496,-218.858 ; 301.645,370.275 303.296,370.275 304.439,371.418 304.439,373.069 ; 301.645,370.275 304.439,373.069 ; 302.089,264.357 302.089,263.151 303.128,262.112 ; 302.089,264.357 302.089,267.088 ; 302.665,-189.256 303.764,-189.256 ; 302.875,-176.556 302.875,-173.299 ; 302.875,-176.556 303.002,-176.683 303.129,-176.683 305.288,-178.842 ; 302.875,-176.556 302.875,-174.778 ; 302.875,-176.556 307.066,-180.747 ; 302.875,-174.778 307.066,-178.969 ; 302.875,-174.778 302.875,-173.299 ; 302.875,-173.299 302.875,-164.491 ; 302.875,-164.491 303.88,-165.496 303.88,-174.016 ; 302.961,-217.323 304.496,-218.858 ; 303.128,260.42 304.566,258.982 304.566,258.515 304.693,258.642 304.693,262.96 ; 303.128,260.42 304.693,261.985 304.693,262.96 ; 303.128,260.42 303.128,267.573 ; 303.128,260.42 303.128,262.112 ; 303.128,262.112 304.058,263.042 304.058,266.643 ; 303.128,267.573 304.058,266.643 ; 303.88,-174.016 312.204,-182.34 ; 304.058,266.643 304.693,266.008 304.693,262.96 ; 304.121,-76.353 304.121,-78.361 305.034,-79.274 316.845,-79.274 318.623,-81.052 ; 304.121,-76.353 304.121,-73.489 304.971,-74.338 304.971,-76.48 ; 304.121,-76.353 304.121,-77.091 304.971,-77.94 ; 304.306,327.973 304.306,328.359 305.328,329.381 ; 304.496,-218.858 311.638,-218.858 ; 304.496,-218.858 305.247,-219.609 ; 304.802,-183.817 304.891,-183.817 306.453,-182.255 ; 304.971,-77.94 304.971,-76.48 ; 304.971,-76.48 304.971,-76.67 306.812,-78.512 317.734,-78.512 318.623,-79.401 318.623,-81.052 ; 305.247,-219.609 320.675,-219.609 ; 305.288,-178.842 306.453,-180.007 306.453,-182.255 ; 305.328,329.381 308.376,332.429 310.675,332.429 311.24,332.994 ; 305.98,272.029 306.921,271.088 310.408,271.088 311.348,272.029 ; 305.98,272.029 311.348,272.029 ; 306.59,219.145 308.749,216.986 ; 306.59,219.145 306.59,220.034 ; 306.59,220.034 306.59,225.611 306.59,225.995 306.09,225.495 306.09,218.256 307.36,216.986 308.749,216.986 ; 306.59,220.034 308.887,217.737 315.054,217.737 ; 307.066,-183.502 307.066,-180.62 ; 307.066,-183.502 309.761,-183.502 310.484,-182.779 308.325,-180.62 307.066,-180.62 ; 307.066,-180.747 307.066,-180.62 ; 307.066,-180.62 307.066,-178.969 ; 307.233,302.965 310.027,302.965 312.948,300.044 ; 307.233,302.965 308.376,302.965 311.297,300.044 312.948,300.044 ; 308.749,216.986 318.876,216.986 ; 311.638,-218.858 312.961,-217.536 ; 311.638,-218.858 314.496,-218.858 ; 312.781,-81.814 313.67,-81.814 ; 312.948,300.044 312.948,298.774 312.313,298.139 307.599,298.139 305.328,295.868 306.994,295.868 308.249,297.123 311.551,297.123 313.075,298.647 313.075,299.917 312.948,300.044 ; 312.961,-217.536 312.961,-217.323 ; 312.961,-217.323 314.496,-218.858 ; 313.202,250.133 313.9,250.832 ; 314.051,-186.252 318.856,-186.252 326.016,-186.252 333.175,-186.252 340.335,-186.252 347.495,-186.252 354.597,-186.252 354.724,-186.125 369.456,-186.125 376.568,-186.125 375.508,-185.065 ; 314.496,-218.858 321.426,-218.858 ; 315.054,217.737 316.59,219.272 ; 315.054,217.737 318.125,217.737 ; 316.294,247.339 317.393,247.339 ; 316.38,-156.871 316.38,-155.855 ; 316.504,260.039 316.504,263.296 ; 316.504,260.039 316.631,259.912 316.758,259.912 318.917,257.753 ; 316.504,260.039 316.504,261.817 ; 316.504,260.039 320.695,255.848 ; 316.504,261.817 320.695,257.626 ; 316.504,261.817 316.504,263.296 ; 316.504,263.296 316.504,272.104 ; 316.504,272.104 317.509,271.1 317.509,262.579 ; 316.59,219.272 318.125,217.737 ; 317.509,262.579 325.833,254.255 ; 317.75,360.242 317.75,358.234 318.663,357.321 330.474,357.321 332.252,355.543 ; 317.75,360.242 317.75,363.106 318.599,362.257 318.599,360.115 ; 317.75,360.242 317.75,359.504 318.599,358.655 ; 318.125,217.737 325.267,217.737 ; 318.125,217.737 318.876,216.986 ; 318.431,252.778 318.519,252.778 320.082,254.341 ; 318.599,358.655 318.599,360.115 ; 318.599,360.115 318.599,359.925 320.441,358.083 331.363,358.083 332.252,357.194 332.252,355.543 ; 318.876,216.986 334.304,216.986 ; 318.917,257.753 320.082,256.588 320.082,254.341 ; 320.675,-219.609 360.548,-219.609 ; 320.675,-219.609 321.426,-218.858 ; 320.695,253.093 320.695,255.975 ; 320.695,253.093 323.39,253.093 324.113,253.816 321.954,255.975 320.695,255.975 ; 320.695,255.848 320.695,255.975 ; 320.695,255.975 320.695,257.626 ; 321.426,-218.858 324.496,-218.858 ; 321.426,-218.858 322.961,-217.323 ; 322.433,-200.443 326.016,-196.861 326.016,-196.368 ; 322.961,-217.323 324.496,-218.858 ; 324.496,-218.858 331.426,-218.858 ; 325.267,217.737 326.59,219.06 ; 325.267,217.737 328.125,217.737 ; 326.41,354.781 327.299,354.781 ; 326.59,219.06 326.59,219.272 ; 326.59,219.272 328.125,217.737 ; 327.68,250.343 332.485,250.343 339.645,250.343 346.804,250.343 353.964,250.343 361.124,250.343 368.226,250.343 368.353,250.47 383.085,250.47 390.197,250.47 389.137,251.53 ; 328.125,217.737 335.054,217.737 ; 330.009,279.724 330.009,280.74 ; 331.426,-218.858 334.496,-218.858 ; 331.426,-218.858 332.961,-217.323 ; 332.961,-217.323 334.496,-218.858 ; 334.304,216.986 374.177,216.986 ; 334.304,216.986 335.054,217.737 ; 334.496,-218.858 341.356,-218.858 ; 335.054,217.737 338.125,217.737 ; 335.054,217.737 336.59,219.272 ; 336.062,236.152 339.645,239.735 339.645,240.227 ; 336.59,219.272 338.125,217.737 ; 338.125,217.737 345.054,217.737 ; 341.356,-218.858 344.623,-218.858 ; 341.356,-218.858 342.961,-217.254 ; 342.961,-217.254 342.961,-217.196 ; 342.961,-217.196 344.623,-218.858 ; 344.623,-218.858 351.426,-218.858 ; 345.054,217.737 348.125,217.737 ; 345.054,217.737 346.59,219.272 ; 346.59,219.272 348.125,217.737 ; 348.125,217.737 354.985,217.737 ; 351.426,-218.858 354.496,-218.858 ; 351.426,-218.858 352.961,-217.323 ; 352.961,-217.323 354.496,-218.858 ; 354.496,-218.858 361.299,-218.858 ; 354.985,217.737 358.252,217.737 ; 354.985,217.737 356.59,219.342 ; 356.59,219.342 356.59,219.399 ; 356.59,219.399 358.252,217.737 ; 358.252,217.737 365.054,217.737 ; 360.548,-219.609 365.105,-219.609 ; 360.548,-219.609 361.299,-218.858 ; 361.299,-218.858 364.355,-218.858 ; 361.299,-218.858 362.961,-217.196 ; 362.961,-217.465 362.961,-217.196 ; 362.961,-217.465 364.355,-218.858 ; 364.355,-218.858 371.235,-218.858 372.961,-217.132 ; 364.355,-218.858 365.105,-219.609 ; 365.054,217.737 368.125,217.737 ; 365.054,217.737 366.59,219.272 ; 365.105,-219.609 371.963,-219.609 372.961,-218.611 372.961,-217.132 ; 366.59,219.272 368.125,217.737 ; 368.125,217.737 374.927,217.737 ; 374.177,216.986 378.734,216.986 ; 374.177,216.986 374.927,217.737 ; 374.927,217.737 377.983,217.737 ; 374.927,217.737 376.59,219.399 ; 376.59,219.131 376.59,219.399 ; 376.59,219.131 377.983,217.737 ; 377.983,217.737 384.864,217.737 386.59,219.463 ; 377.983,217.737 378.734,216.986 ; 378.734,216.986 385.592,216.986 386.59,217.984 386.59,219.463 ; 415.137,-179.477 416.298,-178.316 ; 417.111,-136.551 417.873,-137.313 421.285,-137.313 424.699,-140.727 423.286,-140.727 420.888,-138.329 ; 417.111,-136.551 418.889,-138.329 420.888,-138.329 ; 420.571,-196.812 419.11,-195.352 419.11,-187.564 419.999,-186.675 419.999,-196.241 420.571,-196.812 ; 420.571,-196.812 428.081,-204.323 428.081,-210.984 ; 421.142,-192.304 429.016,-200.178 429.016,-201.575 ; 421.142,-192.304 421.142,-195.479 428.081,-202.418 428.081,-210.984 ; 422.476,-205.321 423.081,-205.927 423.081,-210.984 422.476,-210.379 422.476,-205.321 ; 424.554,-65.748 425.126,-66.32 429.016,-66.32 ; 424.554,-65.748 425.368,-64.934 428.762,-64.934 ; 424.571,-156.871 424.571,-162.02 425.951,-163.399 ; 424.571,-156.871 425.951,-158.25 425.951,-163.399 ; 425.951,-167.14 424.698,-165.888 424.698,-164.745 425.951,-163.492 425.951,-163.399 ; 425.951,-167.14 425.951,-165.997 ; 425.951,-165.997 429.461,-169.507 ; 425.951,-165.997 425.951,-163.399 ; 425.951,-163.399 425.951,-164.473 430.499,-169.022 ; 428.081,-210.984 429.016,-210.049 429.016,-201.575 ; 428.762,-64.934 430.402,-64.934 431.81,-63.526 ; 428.766,257.118 429.927,258.279 ; 429.016,-66.32 430.667,-66.32 431.81,-65.177 431.81,-63.526 ; 429.016,-66.32 431.81,-63.526 ; 429.461,-172.238 429.461,-173.444 430.499,-174.483 ; 429.461,-172.238 429.461,-169.507 ; 430.499,-176.175 431.937,-177.613 431.937,-178.08 432.064,-177.953 432.064,-173.635 ; 430.499,-176.175 432.064,-174.61 432.064,-173.635 ; 430.499,-176.175 430.499,-169.022 ; 430.499,-176.175 430.499,-174.483 ; 430.499,-174.483 431.429,-173.553 431.429,-169.952 ; 430.499,-169.022 431.429,-169.952 ; 430.74,300.044 431.502,299.282 434.914,299.282 438.328,295.868 436.915,295.868 434.517,298.266 ; 430.74,300.044 432.518,298.266 434.517,298.266 ; 431.429,-169.952 432.064,-170.587 432.064,-173.635 ; 431.677,-108.622 431.677,-108.236 432.699,-107.214 ; 432.699,-107.214 435.747,-104.166 438.046,-104.166 438.611,-103.601 ; 433.352,-164.566 434.292,-165.507 437.779,-165.507 438.72,-164.566 ; 433.352,-164.566 438.72,-164.566 ; 433.961,-217.45 436.12,-219.609 ; 433.961,-217.45 433.961,-216.561 ; 433.961,-216.561 433.961,-210.984 433.961,-210.6 433.461,-211.1 433.461,-218.339 434.731,-219.609 436.12,-219.609 ; 433.961,-216.561 436.258,-218.858 442.426,-218.858 ; 434.199,239.783 432.739,241.243 432.739,249.031 433.628,249.92 433.628,240.354 434.199,239.783 ; 434.199,239.783 441.71,232.273 441.71,225.611 ; 434.604,-133.63 437.398,-133.63 440.319,-136.551 ; 434.604,-133.63 435.747,-133.63 438.668,-136.551 440.319,-136.551 ; 434.771,244.291 442.645,236.417 442.645,235.02 ; 434.771,244.291 434.771,241.116 441.71,234.178 441.71,225.611 ; 436.104,231.274 436.71,230.669 436.71,225.611 436.104,226.216 436.104,231.274 ; 436.12,-219.609 446.247,-219.609 ; 438.183,370.848 438.755,370.275 442.645,370.275 ; 438.183,370.848 438.996,371.661 442.391,371.661 ; 438.2,279.724 438.2,274.575 439.579,273.196 ; 438.2,279.724 439.579,278.345 439.579,273.196 ; 439.579,269.455 438.327,270.707 438.327,271.85 439.579,273.103 439.579,273.196 ; 439.579,269.455 439.579,270.598 ; 439.579,270.598 443.089,267.088 ; 439.579,270.598 439.579,273.196 ; 439.579,273.196 439.579,272.122 444.128,267.573 ; 440.319,-136.551 440.319,-137.821 439.684,-138.456 434.97,-138.456 432.699,-140.727 434.365,-140.727 435.62,-139.472 438.922,-139.472 440.446,-137.948 440.446,-136.678 440.319,-136.551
